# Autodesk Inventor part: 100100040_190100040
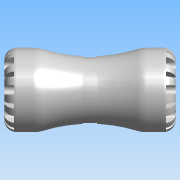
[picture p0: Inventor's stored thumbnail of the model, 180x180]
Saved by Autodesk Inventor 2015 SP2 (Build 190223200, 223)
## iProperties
Created: 2016-12
Part Number: 100100040_190100040
Material: PVC-Piping
Description: PLASSON COUPLER 40X40 SERIES 1
Document SubType Name: Modeling
Designer: KIM
Mass: 95.2094 g
Surface Area: 200.83 cm^2
Volume: 68.0067 cm^3
Density: 1.4 g/cm^3
Appearance: Smooth - White
ILogicFactory: False
Author: KIM
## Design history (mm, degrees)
derived "1001.ipt"
feature "Solid1::1001.ipt"
tag "TaggingFeature1"
body "Solid1"
other parameters: "d4" = 3.33333, "d11" = 8, "d13" = 8, "d14" = 0, "d16" = 360 deg, "d18" = 8 deg, "d19" = 0.8, "d20" = 8 deg, "d21" = 0.8, "d23" = 0, "d25" = 360 deg, "d27" = 28, "d29" = 12, "d30" = 16, "d31" = 0, "d33" = 0, "d37" = 28.4, "d38" = 0.7, "d43" = 5, "d45" = 28.4, "d46" = 56, "d48" = 142, "d50" = 360 deg, "d54" = 0.513, "H_" = 142
